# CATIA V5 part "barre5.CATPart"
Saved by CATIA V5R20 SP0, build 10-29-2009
Part number: barre5
Bounding box of the stored display mesh (mm): x -20 to -10, y -238.987 to 100.105, z 91.181 to 154.244
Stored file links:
  D:\Dropbox\IAO_2012\IAO_2012_748_omeyer\omeyer\omeyer\barre5.CATPart
  U:\Projet IAO\omeyer\Catia\Ass_748_skl.CATProduct
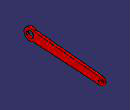
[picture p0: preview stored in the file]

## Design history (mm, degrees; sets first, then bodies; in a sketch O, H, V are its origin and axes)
Set1
  Plane1 "PlanRef": linked copy from another document
  DatumPoint1 "PointG": linked copy from another document
  DatumPoint2 "PointF": linked copy from another document
Body1 (main body)
  Sketch1 on Plane1, origin (0, 0, 0), H (0, 1, 0), V (0, 0, 1)
    arc A1 centre (85.1115, 106.172) radius 15 from (84.2073, 91.1992) to (86.5142, 121.1062) ccw
    point P1 (85.1115, 106.172)
    arc A2 centre (-214, 129.244) radius 25 from (-197.1955, 147.7536) to (-200.2328, 108.3761) ccw
    point P2 (-214, 129.244)
    reference projected point E1 (-214, 129.244) from DatumPoint1
    reference projected point E2 (85.1115, 106.172) from DatumPoint2
    line L1 (86.5142, 121.1062) -> (-197.1955, 147.7536)
    line L2 (84.2073, 91.1992) -> (-200.2328, 108.3761)
    reference projected point E3 (-214, 129.244) from DatumPoint1
    reference projected point E4 (-214, 129.244) from DatumPoint1
    circle A3 centre (85.1115, 106.172) radius 7.5
    point P7 (85.1115, 106.172)
    circle A4 centre (-214, 129.244) radius 15
    point P8 (-214, 129.244)
    reference projected point E5 (-214, 129.244) from DatumPoint1
    reference projected point E6 (85.1115, 106.172) from DatumPoint2
    radius A1 = 15
    radius A2 = 25
    distance L1 E3 = 20
    distance L2 E4 = 20
    radius A3 = 7.5
    radius A4 = 15
    coincidence: P2 E1, P1 E2, P8 E5, P7 E6
    tangency: L2 A1, L1 A1
  Pad1: profile Sketch1, direction (-1, 0, 0), length 20, opposite side length -10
